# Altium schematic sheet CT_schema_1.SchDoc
size 352 x 258 mm
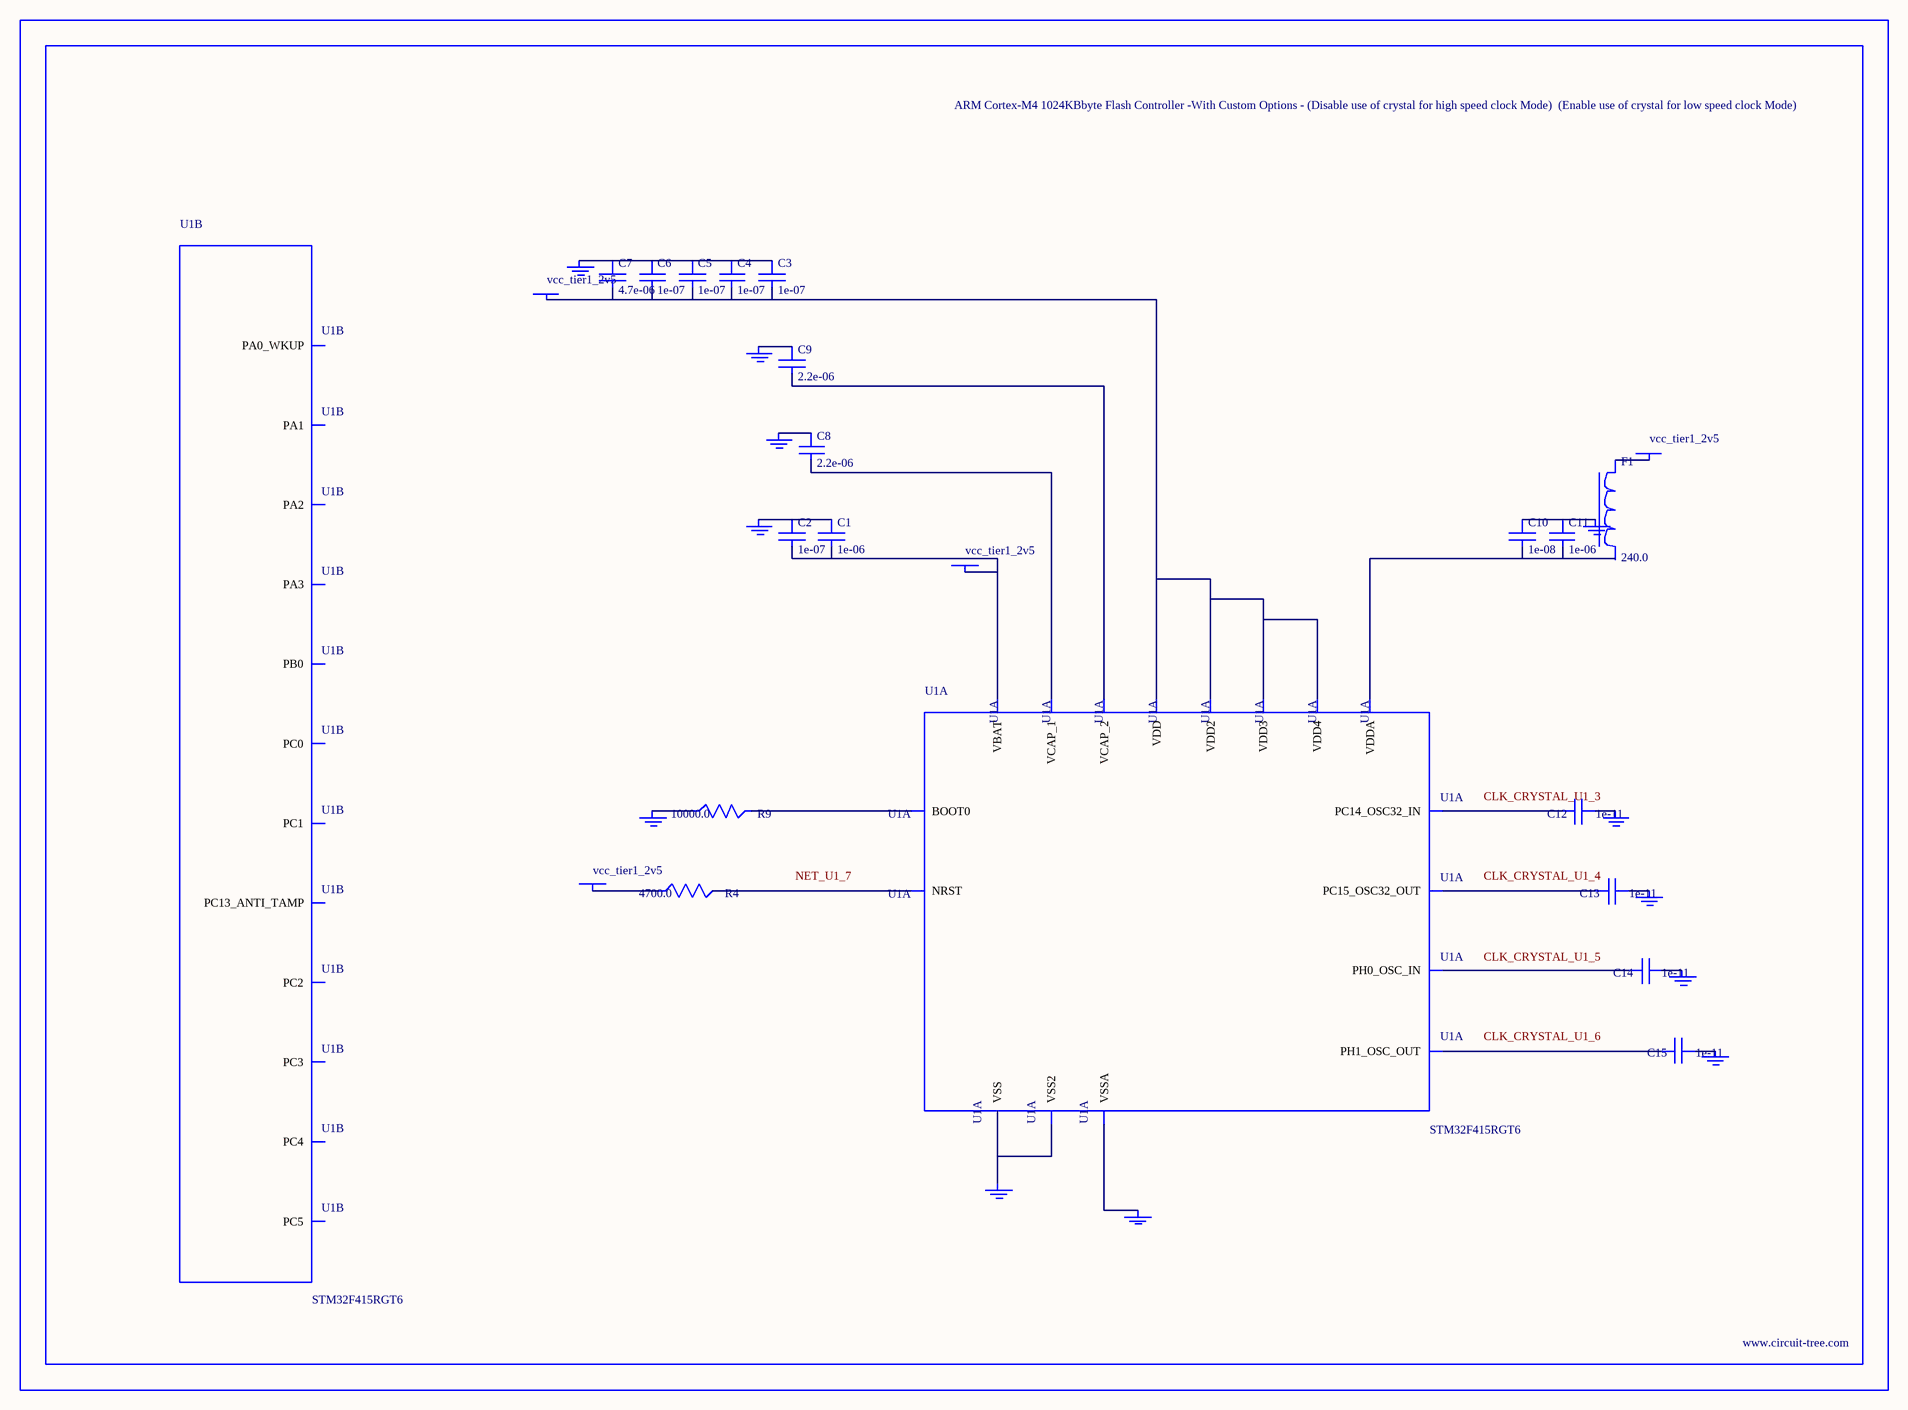
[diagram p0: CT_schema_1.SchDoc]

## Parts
BORDER0  (no value)
C1  1e-06  [C0603]
C2  1e-07  [C0603]
C3  1e-07  [C0603]
C4  1e-07  [C0603]
C5  1e-07  [C0603]
C6  1e-07  [C0603]
C7  4.7e-06  [C0603]
C8  2.2e-06  [C0603]
C9  2.2e-06  [C0603]
C10  1e-08  [C0603]
C11  1e-06  [C0603]
C12  1e-11  [C0402]
C13  1e-11  [C0402]
C14  1e-11  [C0402]
C15  1e-11  [C0402]
F1  240.0  [L0603]
GND_INSTANCE_0_0  (no value)
GND_INSTANCE_0_1  (no value)
GND_INSTANCE_0_2  (no value)
GND_INSTANCE_0_3  (no value)
GND_INSTANCE_0_4  (no value)
GND_INSTANCE_0_5  (no value)
GND_INSTANCE_0_6  (no value)
GND_INSTANCE_0_7  (no value)
GND_INSTANCE_0_8  (no value)
GND_INSTANCE_0_9  (no value)
GND_INSTANCE_0_10  (no value)
GND_INSTANCE_0_11  (no value)
POWER_INSTANCE_0_0  vcc_tier1_2v5
POWER_INSTANCE_0_1  vcc_tier1_2v5
POWER_INSTANCE_0_2  vcc_tier1_2v5
POWER_INSTANCE_0_3  vcc_tier1_2v5
R4  4700.0  [R0603]
R9  10000.0  [R0603]
U1  STM32F415RGT6  [LQFP64]  (parts A,B of 7)

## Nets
NetC1_1: C1.1 C2.1 GND_INSTANCE_0_0.0(GND)
NetC1_2: C1.2 C2.2 POWER_INSTANCE_0_0.0(PWR) U1.1(VBAT)
NetC3_1: C3.1 C4.1 C5.1 C6.1 C7.1 GND_INSTANCE_0_7.0(GND)
NetC3_2: C3.2 C4.2 C5.2 C6.2 C7.2 POWER_INSTANCE_0_2.0(PWR) U1.19(VDD) U1.32(VDD2) U1.48(VDD3) U1.64(VDD4)
NetC8_1: C8.1 GND_INSTANCE_0_8.0(GND)
NetC8_2: C8.2 U1.31(VCAP_1)
NetC9_1: C9.1 GND_INSTANCE_0_9.0(GND)
NetC9_2: C9.2 U1.47(VCAP_2)
NetC10_1: C10.1 C11.1 GND_INSTANCE_0_6.0(GND)
NetC10_2: C10.2 C11.2 U1.13(VDDA)
NetC12_1: C12.1 GND_INSTANCE_0_1.0(GND)
NetC12_2: C12.2 U1.3(PC14_OSC32_IN)
NetC13_1: C13.1 GND_INSTANCE_0_2.0(GND)
NetC13_2: C13.2 U1.4(PC15_OSC32_OUT)
NetC14_1: C14.1 GND_INSTANCE_0_3.0(GND)
NetC14_2: C14.2 U1.5(PH0_OSC_IN)
NetC15_1: C15.1 GND_INSTANCE_0_4.0(GND)
NetC15_2: C15.2 U1.6(PH1_OSC_OUT)
NetF1_1: F1.1 POWER_INSTANCE_0_1.0(PWR)
NetGND_INSTANCE_0_5_0: GND_INSTANCE_0_5.0(GND) U1.12(VSSA)
NetGND_INSTANCE_0_10_0: GND_INSTANCE_0_10.0(GND) R9.1
NetGND_INSTANCE_0_11_0: GND_INSTANCE_0_11.0(GND) U1.18(VSS) U1.63(VSS2)
NetPOWER_INSTANCE_0_3_0: POWER_INSTANCE_0_3.0(PWR) R4.1
NetR4_2: R4.2 U1.7(NRST)
NetR9_2: R9.2 U1.60(BOOT0)

Not connected (* = marked no-connect by the designer): F1 2; U1 2(PC13_ANTI_TAMP) 8(PC0) 9(PC1) 10(PC2) 11(PC3) 14(PA0_WKUP) 15(PA1) 16(PA2) 17(PA3) 24(PC4) 25(PC5) 26(PB0)

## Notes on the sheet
- Labels drawn without touching a wire or pin: CLK_CRYSTAL_U1_3, CLK_CRYSTAL_U1_4, CLK_CRYSTAL_U1_5, CLK_CRYSTAL_U1_6, NET_U1_7

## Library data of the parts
BORDER0 = BORDER_PAGE0
C1 C11 = C0603C105K3RACTU
C2-C6 = 06035C104K4Z2A
C7 = GRM188R6YA475KE15D
C8 C9 = C0603C225K8RACTU
C10 = 06035C103K4Z2A
C12-C15 = C0402C100K3GACTU
F1 = Z0603C241ASMST
GND_INSTANCE_0_0-GND_INSTANCE_0_11 = GND
POWER_INSTANCE_0_0-POWER_INSTANCE_0_3 = PWR
R4 = RC0603JR-074K7L
R9 = RC0603JR-0710KL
